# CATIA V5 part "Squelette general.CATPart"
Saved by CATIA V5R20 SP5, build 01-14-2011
Part number: Squelette general
Publications: "Point.1", "Point.2", "Point.3", "Point.5", "Point.6", "Point.7", "Point.8", "Point.16", "Point.22", "Point.23", "Point.24", "Point.25", "Point.26", "Point.31", "Point.35", "Point.36", "Point.37", "Point.44", "Point.45", "Droite.28", "Point.46", "Point.47", "Point.54", "Point.57", "Point.59", "Point.60", "Point.61", "Point.62", "Point.63", "Point.64", "Point.65", "Point.66", "Point.67", "Point.68", "Point.69", "Point.70", "Point.71", "Point.72", "Point.73", "Point.74", "Droite.39", "Point.75", "Longueur bielle 2", "Hauteur bielle L", "Longueur bielle L", "Decalage", "Longueur Bielle 3-4", "Hauteur Bielle principale", "Longueur Bielle principale", "Longueur Avant Bras", "Hauteur Avant Bras", "Point.76"
Bounding box of the stored display mesh (mm): x -350 to 0, y -325 to 100, z -40 to 80
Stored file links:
  U:\CFAO\Thinkmotion\Squelette general.CATPart
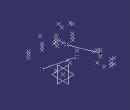
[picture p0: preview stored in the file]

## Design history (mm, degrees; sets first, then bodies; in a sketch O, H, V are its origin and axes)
Parameters
  `Longueur bielle 2` = 200 mm
  `Hauteur bielle L` = 50 mm
  `Longueur bielle L` = 100 mm
  Decalage = 20 mm
  `Longueur Bielle 3-4` = 200 mm
  `Hauteur Bielle principale` = 350 mm
  `Longueur Bielle principale` = 50 mm
  `Longueur Avant Bras` = 20 mm
  `Hauteur Avant Bras` = 300 mm
  `Longueur corps de verin` = 150 mm
Set1
  Point1: (0, 0, 0)
  Plane1 "Plan reference 1": type Offset, RefPlane xy-plane, Offset 0
  Point2: (0, -50 {= -`Hauteur bielle L`}, 0)
  Point3: (-100 {= -`Longueur bielle L`}, -50 {= -`Hauteur bielle L`}, 0)
  Point4: (0, -250 {= -(`Hauteur bielle L` +`Longueur bielle 2` )}, 20 {= Decalage})
  Point5: (0, -250 {= -(`Hauteur bielle L` +`Longueur bielle 2` )}, -20 {= -Decalage})
  Point6: (-200 {= -`Longueur Bielle 3-4`}, -250 {= -(`Hauteur bielle L` +`Longueur bielle 2` )}, 20 {= Decalage})
  Point7: (-200 {= -`Longueur Bielle 3-4`}, -250 {= -(`Hauteur bielle L` +`Longueur bielle 2` )}, -20 {= -Decalage})
  Point8: (-200 {= -`Longueur Bielle 3-4`}, 100 {= -(`Hauteur bielle L` +`Longueur bielle 2` )+`Hauteur Bielle principale`}, 0)
  Point9: (0, 0, -20 {= -Decalage}), relative to Point39
  Point10: (0, 0, 20 {= Decalage}), relative to Point39
  Point11: (-20 {= -`Longueur Avant Bras`}, 0, 0), relative to Point10
  Point12: (-20 {= -`Longueur Avant Bras`}, 0, 0), relative to Point9
  Point13: (0, -100 {= -(100/300)*`Hauteur Avant Bras`}, 0), relative to Point12
  Point14: (0, -300 {= -`Hauteur Avant Bras`}, 0), relative to Point12
  Point15: (0, 0, 80 {= 60mm+Decalage}), relative to Point38
  Point16: (0, 0, 60), relative to Point31
  Point17: (0, 0, 20 {= Decalage}), relative to Point14
  Point18: (0, 0, -40), relative to Point37
  Point19: (0, -150, -40)
  Line1: type PtPt, FirstPoint Point19, SecondPoint Point18
  Point20: type OnCurve, Support Line1, Length 150
  Point21: (50 {= `Longueur Bielle principale`}, -50 {= -`Longueur Bielle principale`}, 0), relative to Point16
  Point22: (40, 0, 0), relative to Point35
  Point23: (0, -100 {= -(100/350)*`Hauteur Bielle principale`}, 0), relative to Point28
  Point24: (-100 {= -`Longueur bielle L`}, -250 {= -(`Longueur bielle 2` +`Hauteur bielle L` )}, 0)
  Point25: (-100 {= -(`Longueur bielle L` )}, -250 {= -(`Hauteur bielle L` +`Longueur bielle 2` )}, 20 {= Decalage})
  Point26: (-100 {= -`Longueur bielle L`}, -250 {= -(`Hauteur bielle L` +`Longueur bielle 2` )}, -20 {= -Decalage})
  Point27: (0, -250 {= -(`Hauteur bielle L` +`Longueur bielle 2` )}, 0)
  Point28: (40, 0, 0), relative to Point34
  Point29: (0, 0, 20 {= Decalage}), relative to Point13
  Point30: (0, -100 {= -(100/300)*`Hauteur Avant Bras`}, 0), relative to Point11
  Point31: (0, 0, 20 {= Decalage}), relative to Point17
  Point32: (-20 {= -Decalage}, -100, 0), relative to Point17
  Point33: (-200 {= -`Longueur Bielle 3-4`}, -250 {= -(`Hauteur bielle L` +`Longueur bielle 2` )}, 0), relative to Point1
  Point34: (0, 25 {= (25/350)*`Hauteur Bielle principale`}, 0), relative to Point33
  Point35: (0, 25 {= (25/350)*`Hauteur Bielle principale`}, 0), relative to Point34
  Point36: (0, 25 {= (25/350)*`Hauteur Bielle principale`}, 0), relative to Point35
  Point37: (0, 75 {= (75/350)*`Hauteur Bielle principale`}, 0), relative to Point36
  Point38: (0, 150 {= (150/350)*`Hauteur Bielle principale`}, 0), relative to Point37
  Point39: (-50 {= -`Longueur Bielle principale`}, 0, 0), relative to Point8
  Line2: type PtPt, FirstPoint Point36, SecondPoint Point29
  Point40: type OnCurve, Support Line2, Length 150 {= `Longueur corps de verin`}
  Point41: (-60 {= -3*Decalage}, 0, 0), relative to Point32
Body1 (main body)
Relations
  Point41.X = -3* (deactivated)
